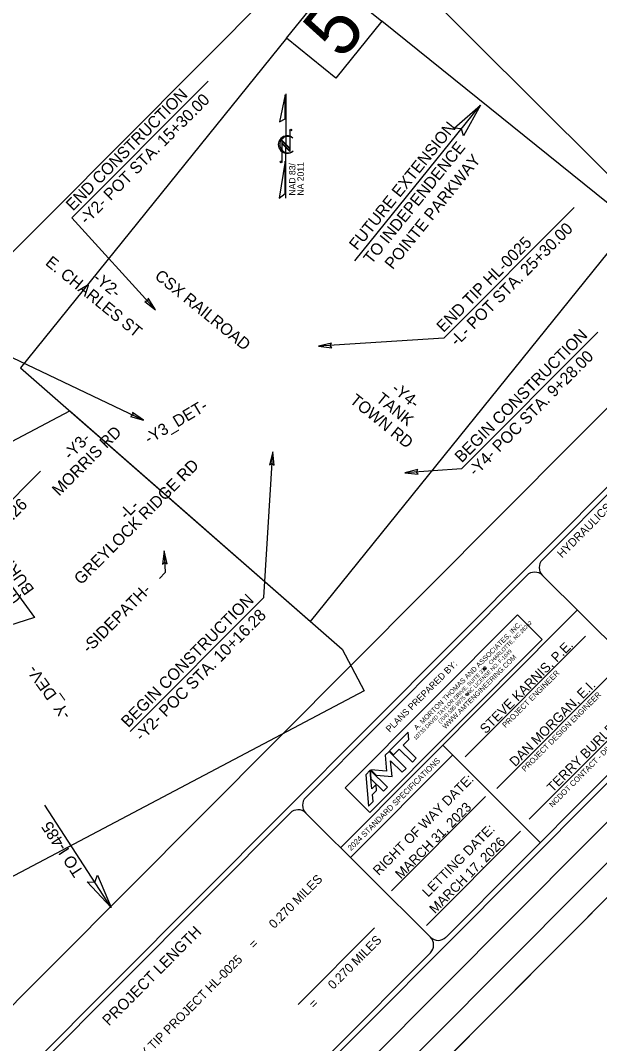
# Model space of a CAD drawing. Extents: x 1481763 to 1495577, y 493394 to 506245.
# Drawn here: x 1488088 to 1489667, y 497417 to 500209 of the extents above; entities that cross this region are included whole.
import ezdxf

# ---------------------------------------------------------------- set-up
doc = ezdxf.new("R2010")
doc.units = 0
for name, color, linetype in [('Prop Dimension', 7, 'Continuous'), ('Prop DSN Text', 7, 'Continuous'), ('Prop DSN White Annotation Label', 7, 'Continuous'), ('Prop Grid Mask', 7, 'Continuous'), ('Prop Horizontal Alignment Station Label', 7, 'Continuous'), ('Prop Terminator CELL', 7, 'Continuous'), ('Scratch_Level_0', 7, 'Continuous'), ('Scratch_Level_4', 7, 'Continuous'), ('Sheet Block Title CELL', 7, 'Continuous'), ('Sheet Cutting Line CELL', 7, 'Continuous'), ('Sheet Data Field CELL', 7, 'Continuous'), ('Sheet North Arrow CELL', 7, 'Continuous'), ('Sheet Plot Border Inside CELL', 7, 'Continuous'), ('Sheet Plot Border Outside CELL', 7, 'Continuous'), ('Sheet Title CELL', 7, 'Continuous')]:
    doc.layers.add(name, color=color, linetype=linetype)

msp = doc.modelspace()

# ---------------------------------------------------------------- linework, layer by layer
at = {"layer": 'Prop Dimension'}
for p, q in [((1488600.1, 500043.2), (1488228.3, 499669.8)), ((1489598, 499698.5), (1489242.3, 499341.4)), ((1488228.3, 499669.8), (1488455.9, 499419.4)), ((1489662.4, 499358), (1489290.8, 498984.9)), ((1489242.3, 499341.4), (1488900.6, 499320)), ((1488009, 499315.3), (1488423.2, 499117.7)), ((1488751.5, 498634.5), (1488775.9, 499031.9)), ((1489290.8, 498984.9), (1489136.4, 498974.5)), ((1488142.6, 498979.2), (1487745.2, 498580.2)), ((1488479.7, 498761.9), (1488482.6, 498702.3)), ((1488482.6, 498702.3), (1488466.7, 498686.4)), ((1488751.5, 498634.5), (1488387.4, 498268.8))]:
    msp.add_line(p, q, dxfattribs=at)
at = {"layer": 'Prop DSN Text'}
for p, q in [((1489000, 499553), (1489342.6, 499977.8)), ((1488335.3, 497788.1), (1488154.6, 498067.2))]:
    msp.add_line(p, q, dxfattribs=at)
at = {"layer": 'Prop DSN White Annotation Label'}
msp.add_lwpolyline([(1488813.3, 500160.1), (1488938.9, 500315.8), (1489073.9, 500206.9)], dxfattribs=at)
for points in [[(1488948.4, 500051.2), (1488813.3, 500160.1), (1488087.8, 499260.5), (1488879.1, 498569.1), (1489756.2, 499656.7), (1489073.9, 500206.9)], [(1487208.7, 498608.1), (1488222.1, 499143.2), (1488965.4, 498493.7), (1489025.4, 498380), (1487698.9, 497679.6)]]:
    msp.add_lwpolyline(points, close=True, dxfattribs=at)
at = {"layer": 'Prop Grid Mask'}
msp.add_lwpolyline([(1488973.3, 498115.1), (1489443.3, 498587.1), (1489511.3, 498519.4), (1489041.2, 498047.5)], close=True, dxfattribs=at)
at = {"layer": 'Prop Terminator CELL'}
for points in [[(1489270.6, 499914.5), (1489342.6, 499977.8), (1489296, 499893.3), (1489290.5, 499913.2)], [(1488427.1, 499441.9), (1488455.9, 499419.4), (1488436.3, 499450.5), (1488434.6, 499442.8)], [(1488936.2, 499328.4), (1488900.6, 499320), (1488937.2, 499315.8), (1488932.2, 499321.9)], [(1488388, 499127.6), (1488423.2, 499117.7), (1488393.3, 499139.1), (1488394.7, 499131.3)], [(1488779.9, 498995.6), (1488775.9, 499031.9), (1488767.3, 498996.2), (1488773.9, 499000.4)], [(1489171.9, 498983.1), (1489136.4, 498974.5), (1489173, 498970.5), (1489168, 498976.6)], [(1488487.6, 498726.2), (1488479.7, 498761.9), (1488475.1, 498725.4), (1488481.2, 498730.3)], [(1488297.6, 497876.3), (1488335.3, 497788.1), (1488269.5, 497858.8), (1488290.2, 497857.8)]]:
    msp.add_lwpolyline(points, close=True, dxfattribs=at)
at = {"layer": 'Scratch_Level_4'}
for points in [[(1486945.7, 498451.8), (1488980.9, 500495.4), (1490008.1, 499472.4), (1487973, 497428.8)], [(1487759, 498462.3), (1487720.6, 498534.8), (1488006.4, 498743.3), (1488126.2, 498579.3)]]:
    msp.add_lwpolyline(points, close=True, dxfattribs=at)
at = {"layer": 'Sheet Block Title CELL'}
msp.add_lwpolyline([(1488973.3, 498115.1), (1489443.3, 498587.1), (1489511.3, 498519.4), (1489041.2, 498047.5)], close=True, dxfattribs=at)
for points in [[(1489167.5, 498195.7), (1489131.6, 498231.5), (1489147, 498247), (1489145.2, 498266.6), (1489094.6, 498215.9), (1489105.3, 498205.2), (1489120.9, 498220.8), (1489156.9, 498185), (1489167.5, 498195.7)], [(1489101.3, 498145.7), (1489097.4, 498189), (1489129.3, 498157.3), (1489139.9, 498168), (1489093.3, 498214.5), (1489082.6, 498203.8), (1489086.2, 498160.8), (1489043.3, 498164.3), (1489058.2, 498149.6), (1489101.3, 498145.7)], [(1489043.9, 498139.8), (1489042, 498163), (1489029.5, 498150.5), (1489037.6, 498065.3), (1489049.7, 498077.4), (1489047.8, 498096.5), (1489058.9, 498107.6), (1489057.7, 498124), (1489046.2, 498112.5), (1489043.9, 498139.8)], [(1489088.6, 498116.5), (1489042, 498163), (1489043.9, 498139.8), (1489078, 498105.8), (1489088.6, 498116.5)]]:
    msp.add_lwpolyline(points, dxfattribs=at)
for centre in [(1489353.7, 498440), (1489305.8, 498369.6)]:
    msp.add_circle(centre, 3, dxfattribs=at)
at = {"layer": 'Sheet Cutting Line CELL'}
msp.add_line((1487357.7, 495475.3), (1490922.5, 499055), dxfattribs=at)
msp.add_lwpolyline([(1485019.4, 497803.9), (1488584.2, 501383.6), (1490922.5, 499055), (1487357.7, 495475.3)], close=True, dxfattribs=at)
at = {"layer": 'Sheet North Arrow CELL'}
for p, q in [((1488812, 499724.1), (1488812.2, 500008.5)), ((1488822.9, 499909.5), (1488822.8, 499851.2)), ((1488822.8, 499860.3), (1488801.1, 499882)), ((1488801.1, 499882), (1488801.1, 499822.7)), ((1488822.8, 499858.1), (1488801.1, 499879.9)), ((1488801.1, 499879.9), (1488801.1, 499874.6)), ((1488830.9, 499887.8), (1488831.2, 499887.6)), ((1488822.8, 499852.8), (1488801.1, 499874.6)), ((1488801.1, 499874.6), (1488822.8, 499852.8)), ((1488822.8, 499851.2), (1488801.1, 499872.9)), ((1488822.8, 499852.8), (1488822.8, 499858.1))]:
    msp.add_line(p, q, dxfattribs=at)
for points in [[(1488810.3, 500006), (1488794, 499932.2), (1488810.2, 499940.4)], [(1488809.8, 499824.3), (1488793.6, 499724.1), (1488809.7, 499736.8)]]:
    msp.add_lwpolyline(points, close=True, dxfattribs=at)
for centre in [(1488825.2, 499909.5), (1488798.7, 499822.6)]:
    msp.add_circle(centre, 2.32, dxfattribs=at)
for centre, radius, start, end in [((1488815.1, 499869.9), 23.9, 47.7961, 312.3501), ((1488817.5, 499869.9), 22.4, 53.0511, 308.5848)]:
    msp.add_arc(centre, radius, start, end, dxfattribs=at)
at = {"layer": 'Sheet Plot Border Inside CELL'}
msp.add_lwpolyline([(1487337.5, 495550.5), (1490865.3, 499093), (1488622.4, 501326.5), (1485094.6, 497784)], close=True, dxfattribs=at)
at = {"layer": 'Sheet Plot Border Outside CELL'}
msp.add_lwpolyline([(1488481.3, 501486.1), (1484916.4, 497906.4), (1487254.7, 495577.9), (1490819.6, 499157.6)], close=True, dxfattribs=at)
at = {"layer": 'Sheet Title CELL'}
for p, q in [((1487288.8, 496526.2), (1490294.8, 499544.7)), ((1489511.6, 498737), (1489934.5, 499161.6)), ((1488865.9, 498088.6), (1489469.2, 498694.4)), ((1489851.8, 498355.8), (1489511.7, 498694.5)), ((1489606.8, 498599.8), (1488961.1, 497951.5)), ((1489300.9, 498199.2), (1489629.4, 498529)), ((1489387.2, 498113.1), (1489718, 498445.2)), ((1489475.8, 498029.3), (1489806.6, 498361.4)), ((1489239.6, 498231.1), (1489505.9, 497965.9)), ((1489266.7, 498204.1), (1488988.2, 497924.5)), ((1489186.5, 498123.5), (1489186.5, 498123.5)), ((1489356.6, 498090.9), (1489100.3, 497833.6)), ((1488019.2, 497238.3), (1488823.6, 498046.1)), ((1488866, 498046.2), (1489206.1, 497707.5)), ((1489451.4, 497996.5), (1489195.1, 497739.2)), ((1489235.3, 497969.1), (1489235.3, 497969.1)), ((1488845.7, 497523.7), (1489053.9, 497732.7))]:
    msp.add_line(p, q, dxfattribs=at)
for points in [[(1487576.3, 496007), (1490709.3, 499153.1)], [(1489248.6, 497707.6), (1489851.9, 498313.4)], [(1488401.8, 496857.2), (1489206.2, 497665)]]:
    msp.add_lwpolyline(points, dxfattribs=at)
for centre, start, end in [((1489532.7, 498715.9), 135.1191, 225.1191), ((1489490.4, 498673.4), 45.1191, 135.1191), ((1488887.1, 498067.5), 135.1191, 225.1191), ((1488844.8, 498025), 45.1191, 135.1191), ((1489227.2, 497728.8), 225.1191, 315.1191), ((1489184.9, 497686.3), 315.1191, 45.1191)]:
    msp.add_arc(centre, 30, start, end, dxfattribs=at)

# ---------------------------------------------------------------- texts
at = {"layer": 'Prop DSN Text'}
for s, height, rotation, p in [('5', 150, 51.1156, (1488964.6, 500098.1)), ('END CONSTRUCTION', 32, 45.1191, (1488230.8, 499687)), ('-Y2- POT STA. 15+30.00', 32, 45.1191, (1488268.2, 499649.8)), ('FUTURE EXTENSION', 32, 51.1158, (1489006.1, 499579.3)), ('TO INDEPENDENCE', 32, 51.1158, (1489045.3, 499541.6)), ('POINTE PARKWAY', 32, 51.1158, (1489103.2, 499527.1)), ('-L- POT STA. 25+30.00', 32, 45.1191, (1489279, 499318.1)), ('END TIP HL-0025', 32, 45.1191, (1489241.6, 499355.3)), ('BEGIN CONSTRUCTION', 32, 45.1191, (1489291.4, 499000.1)), ('-Y4- POC STA. 9+28.00', 32, 45.1191, (1489328.8, 498962.9)), ('-L- POT STA. 11+04.26', 32, 45.1191, (1487790.8, 498565.9)), ('BEGIN CONSTRUCTION', 32, 45.1191, (1488381.4, 498277.5)), ('-Y2- POC STA. 10+16.28', 32, 45.1191, (1488418.8, 498240.3)), ('TO I-485', 32, 122.9223, (1488261.4, 497885.1))]:
    msp.add_text(s, height=height, rotation=rotation, dxfattribs=at).set_placement(p)
at = {"layer": 'Prop Horizontal Alignment Station Label'}
for s, rotation, p in [('E. CHARLES ST', 320.9673, (1488153.4, 499543.8)), ('-Y2-', 320.9673, (1488283.1, 499500.5)), ('CSX RAILROAD', 320.9673, (1488451.5, 499506.6)), ('-Y4-', 320.9673, (1489097.8, 499198.8)), ('TOWN RD', 320.9673, (1488983.8, 499167.6)), ('TANK', 320.9673, (1489055.2, 499171.6)), ('-Y3_DET-', 30.8554, (1488438.1, 499051.3)), ('MORRIS RD', 45.1191, (1488193.2, 498909.2)), ('-Y3-', 45.1191, (1488223.8, 499008)), ('GREYLOCK RIDGE RD', 45.1191, (1488253.2, 498667)), ('-L-', 45.1191, (1488376.4, 498845)), ('-SIDEPATH-', 45.1191, (1488274.8, 498480.3))]:
    msp.add_text(s, height=32, rotation=rotation, dxfattribs=at).set_placement(p)
at = {"layer": 'Scratch_Level_0'}
for s, p in [('(FUTURE SELMA ', (1488087.7, 498627.8)), ('BURKE LN)', (1488126.8, 498655.8)), ('-Y_DEV-', (1488227.2, 498315))]:
    msp.add_text(s, height=32, rotation=125.5902, dxfattribs=at).set_placement(p)
at = {"layer": 'Sheet Block Title CELL'}
for s, height, p in [('10735 DAVID TAYLOR DRIVE, SUITE 310   CHARLOTTE, NC 28262', 10.5, (1489166.1, 498244.5)), ('A. MORTON THOMAS AND ASSOCIATES, INC.', 13.5, (1489168.9, 498271.8)), ('(704) 595-9975   NC LICENSE NO. F-1049', 10.5, (1489233.1, 498289.5)), ('WWW.AMTENGINEERING.COM', 13.5, (1489246.9, 498274.6))]:
    msp.add_text(s, height=height, rotation=45.1186, dxfattribs=at).set_placement(p)
at = {"layer": 'Sheet Data Field CELL'}
for s, p in [('STEVE KARNIS, P.E.', (1489356.8, 498260.8)), ('DAN MORGAN, E.I.', (1489437.4, 498170.9)), ('TERRY BURLESON', (1489539.8, 498101.1)), ('MARCH 31, 2023', (1489125.9, 497864.7)), ('MARCH 17, 2026', (1489218.7, 497770))]:
    msp.add_text(s, height=26.25, rotation=45.1191, dxfattribs=at).set_placement(p)
at = {"layer": 'Sheet North Arrow CELL'}
for s, p in [('NA 2011', (1488860.7, 499730.8)), ('NAD 83/', (1488837.8, 499730.8))]:
    msp.add_text(s, height=17.5, rotation=89.9561, dxfattribs=at).set_placement(p)
at = {"layer": 'Sheet Title CELL'}
for s, height, p in [(' HYDRAULICS ENGINEER', 22.5, (1489559.2, 498734.8)), ('PLANS PREPARED BY:', 17.998, (1489095.1, 498264.8)), ('PROJECT ENGINEER', 14.998, (1489410.8, 498277.6)), ('PROJECT DESIGN ENGINEER', 14.998, (1489464.1, 498158.1)), ('NCDOT CONTACT - DIVISION 10', 14.998, (1489538.9, 498060.5)), ('2024 STANDARD SPECIFICATIONS', 15.6, (1488989.6, 497942.1)), ('RIGHT OF WAY DATE: ', 26.249, (1489064.9, 497874.1)), ('LETTING DATE:', 26.249, (1489199.7, 497815.4)), ('0.270 MILES', 24.506, (1488780.1, 497729.4)), ('PROJECT LENGTH', 29.999, (1488328.9, 497463.7)), ('=', 24.5, (1488725.1, 497674.1)), ('0.270 MILES', 24.506, (1488941.2, 497563.5)), ('LENGTH OF ROADWAY TIP PROJECT HL-0025', 24.506, (1488185.4, 497132.2)), ('=', 24.5, (1488888.9, 497511))]:
    msp.add_text(s, height=height, rotation=45.1191, dxfattribs=at).set_placement(p)

doc.saveas('drawing.dxf')
